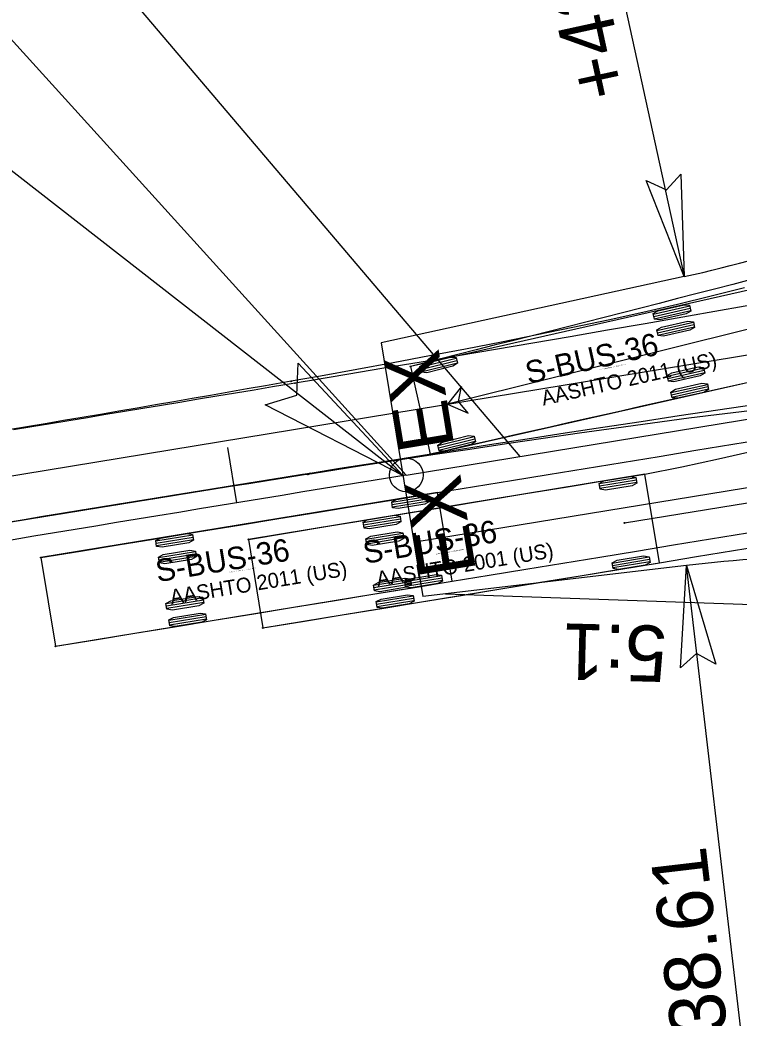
# Model space of a CAD drawing. Extents: x 2367848 to 2369479, y 800728 to 808616.
# Drawn here: x 2368247.5 to 2368311.6, y 807886 to 807974.9 of the extents above; entities that cross this region are included whole.
import ezdxf

# ---------------------------------------------------------------- set-up
doc = ezdxf.new("R2010")
doc.units = 0
for name, color, linetype in [('Prop AutoTurn Projected Path', 7, 'Continuous'), ('Prop AutoTurn Simulation', 7, 'Continuous'), ('Prop Dimension', 7, 'Continuous'), ('Prop Dimension Text', 7, 'Continuous'), ('Prop EOT', 7, 'Continuous'), ('Prop Horizontal Alignment', 7, 'Continuous'), ('Prop Horizontal Alignment Station Label', 7, 'Continuous'), ('Prop Horizontal Alignment Tick Small', 7, 'Continuous'), ('Prop Paved Shoulder', 7, 'Continuous'), ('Prop Terminator CELL', 7, 'Continuous'), ('Scratch_Level_0', 7, 'Continuous'), ('Scratch_Level_1', 7, 'Continuous')]:
    doc.layers.add(name, color=color, linetype=linetype)

msp = doc.modelspace()

# ---------------------------------------------------------------- linework, layer by layer
at = {"layer": 'Prop AutoTurn Projected Path'}
for p, q in [((2368204.585, 807927.346), (2368346.13, 807950.643)), ((2368301.356, 807930.099), (2368335.962, 807935.795))]:
    msp.add_line(p, q, dxfattribs=at)
at = {"layer": 'Prop AutoTurn Simulation'}
for p, q in [((2368303.173, 807934.452), (2368267.848, 807928.638)), ((2368304.472, 807926.558), (2368303.173, 807934.452)), ((2368303.173, 807934.452), (2368303.173, 807934.452)), ((2368302.384, 807934.111), (2368299.095, 807933.57)), ((2368302.418, 807933.905), (2368299.129, 807933.364)), ((2368302.452, 807933.7), (2368299.163, 807933.159)), ((2368281.367, 807930.652), (2368278.078, 807930.11)), ((2368281.401, 807930.446), (2368278.112, 807929.905)), ((2368281.435, 807930.241), (2368278.146, 807929.699)), ((2368281.611, 807929.172), (2368278.322, 807928.63)), ((2368281.645, 807928.966), (2368278.356, 807928.425)), ((2368267.848, 807928.638), (2368269.147, 807920.744)), ((2368281.679, 807928.761), (2368278.389, 807928.219)), ((2368269.147, 807920.744), (2368304.472, 807926.558)), ((2368303.548, 807927.039), (2368300.259, 807926.498)), ((2368303.582, 807926.834), (2368300.293, 807926.293)), ((2368303.616, 807926.628), (2368300.327, 807926.087)), ((2368282.288, 807925.06), (2368278.999, 807924.519)), ((2368282.321, 807924.855), (2368279.032, 807924.313)), ((2368282.355, 807924.649), (2368279.066, 807924.108)), ((2368282.531, 807923.58), (2368279.242, 807923.039)), ((2368282.565, 807923.375), (2368279.276, 807922.833)), ((2368282.599, 807923.169), (2368279.31, 807922.628))]:
    msp.add_line(p, q, dxfattribs=at)
for points in [[(2368312.042, 807951.032), (2368309.084, 807950.286), (2368306.066, 807949.56), (2368302.998, 807948.856), (2368299.89, 807948.17), (2368296.751, 807947.502), (2368293.585, 807946.85), (2368290.399, 807946.213), (2368287.195, 807945.588), (2368283.977, 807944.975), (2368280.748, 807944.371), (2368277.509, 807943.776), (2368274.262, 807943.188), (2368271.66, 807942.723)], [(2368313.273, 807949.613), (2368309.9, 807949.017), (2368306.539, 807948.427), (2368303.189, 807947.843), (2368299.848, 807947.264), (2368296.514, 807946.691), (2368293.186, 807946.121), (2368289.864, 807945.555), (2368286.546, 807944.993), (2368283.233, 807944.433), (2368279.922, 807943.876), (2368276.614, 807943.321), (2368273.309, 807942.767), (2368271.987, 807942.547)], [(2368271.66, 807942.723), (2368271.008, 807942.607), (2368269.379, 807942.319), (2368267.749, 807942.031), (2368266.118, 807941.745), (2368264.485, 807941.461), (2368262.852, 807941.177), (2368261.217, 807940.894), (2368259.582, 807940.612), (2368257.946, 807940.331), (2368256.309, 807940.05), (2368254.672, 807939.771), (2368253.034, 807939.492), (2368251.396, 807939.213), (2368249.757, 807938.935), (2368248.117, 807938.658), (2368246.477, 807938.381)], [(2368271.987, 807942.547), (2368271.657, 807942.491), (2368270.005, 807942.216), (2368268.354, 807941.94), (2368266.704, 807941.665), (2368265.053, 807941.391), (2368263.403, 807941.116), (2368261.754, 807940.842), (2368260.104, 807940.568), (2368258.455, 807940.295), (2368256.806, 807940.021), (2368255.158, 807939.748), (2368253.509, 807939.475), (2368251.861, 807939.202), (2368250.213, 807938.929), (2368248.565, 807938.656), (2368246.917, 807938.384)], [(2368313.119, 807940.657), (2368309.664, 807940.143), (2368306.233, 807939.63), (2368302.823, 807939.116), (2368299.43, 807938.601), (2368296.053, 807938.084), (2368292.689, 807937.564), (2368289.335, 807937.043), (2368285.991, 807936.519), (2368282.655, 807935.993), (2368279.326, 807935.466), (2368276.002, 807934.937), (2368273.347, 807934.512)], [(2368313.496, 807940.212), (2368310.296, 807939.826), (2368307.079, 807939.419), (2368303.848, 807938.992), (2368300.607, 807938.549), (2368297.356, 807938.092), (2368294.098, 807937.622), (2368290.835, 807937.143), (2368287.567, 807936.654), (2368284.295, 807936.158), (2368281.019, 807935.655), (2368277.742, 807935.147), (2368274.461, 807934.634), (2368273.149, 807934.427)], [(2368267.848, 807928.638), (2368271.381, 807929.219), (2368274.913, 807929.801), (2368278.446, 807930.382), (2368281.978, 807930.963), (2368285.511, 807931.545), (2368289.043, 807932.126), (2368292.576, 807932.708), (2368296.108, 807933.289), (2368299.64, 807933.871), (2368303.172, 807934.455), (2368303.172, 807934.455), (2368306.452, 807935.098), (2368309.726, 807935.801), (2368313, 807936.559)], [(2368273.347, 807934.512), (2368272.683, 807934.406), (2368271.025, 807934.14), (2368269.369, 807933.873), (2368267.713, 807933.607), (2368266.058, 807933.34), (2368264.403, 807933.073), (2368262.75, 807932.805), (2368261.097, 807932.538), (2368259.445, 807932.27), (2368257.793, 807932.002), (2368256.142, 807931.734), (2368254.491, 807931.465), (2368252.84, 807931.197), (2368251.191, 807930.928), (2368249.541, 807930.659), (2368247.892, 807930.39), (2368246.243, 807930.121)], [(2368273.149, 807934.427), (2368272.821, 807934.376), (2368271.18, 807934.117), (2368269.538, 807933.857), (2368267.896, 807933.596), (2368266.254, 807933.334), (2368264.612, 807933.072), (2368262.969, 807932.809), (2368261.326, 807932.546), (2368259.683, 807932.282), (2368258.039, 807932.017), (2368256.396, 807931.752), (2368254.752, 807931.486), (2368253.108, 807931.221), (2368251.464, 807930.954), (2368249.82, 807930.688), (2368248.175, 807930.421), (2368246.531, 807930.154)], [(2368269.147, 807920.744), (2368272.68, 807921.325), (2368276.212, 807921.907), (2368279.745, 807922.488), (2368283.277, 807923.07), (2368286.81, 807923.651), (2368290.342, 807924.232), (2368293.875, 807924.814), (2368297.407, 807925.395), (2368300.94, 807925.977), (2368304.472, 807926.558), (2368304.472, 807926.558), (2368304.472, 807926.558), (2368307.768, 807927.101), (2368311.064, 807927.643), (2368314.36, 807928.186)]]:
    msp.add_lwpolyline(points, dxfattribs=at)
for points in [[(2368302.376, 807934.162), (2368302.461, 807933.649), (2368302.026, 807933.419), (2368299.657, 807933.029), (2368299.171, 807933.108), (2368299.087, 807933.621), (2368299.522, 807933.851), (2368301.89, 807934.241)], [(2368281.359, 807930.703), (2368281.443, 807930.19), (2368281.008, 807929.959), (2368278.64, 807929.569), (2368278.154, 807929.648), (2368278.07, 807930.161), (2368278.505, 807930.392), (2368280.873, 807930.782)], [(2368281.602, 807929.223), (2368281.687, 807928.71), (2368281.252, 807928.479), (2368278.884, 807928.089), (2368278.398, 807928.168), (2368278.313, 807928.681), (2368278.748, 807928.912), (2368281.117, 807929.301)], [(2368303.54, 807927.09), (2368303.624, 807926.577), (2368303.189, 807926.347), (2368300.821, 807925.957), (2368300.335, 807926.036), (2368300.251, 807926.549), (2368300.686, 807926.779), (2368303.054, 807927.169)], [(2368282.279, 807925.111), (2368282.364, 807924.598), (2368281.929, 807924.368), (2368279.56, 807923.978), (2368279.075, 807924.057), (2368278.99, 807924.57), (2368279.425, 807924.8), (2368281.793, 807925.19)], [(2368282.523, 807923.631), (2368282.607, 807923.118), (2368282.172, 807922.888), (2368279.804, 807922.498), (2368279.318, 807922.577), (2368279.234, 807923.09), (2368279.669, 807923.32), (2368282.037, 807923.71)]]:
    msp.add_lwpolyline(points, close=True, dxfattribs=at)
for centre in [(2368271.66, 807942.723), (2368271.66, 807942.723), (2368271.987, 807942.547), (2368271.987, 807942.547), (2368273.149, 807934.427), (2368273.149, 807934.427), (2368273.347, 807934.512), (2368273.347, 807934.512), (2368301.356, 807930.099), (2368267.848, 807928.638), (2368269.147, 807920.744)]:
    msp.add_circle(centre, 0.0417, dxfattribs=at)
at = {"layer": 'Prop Dimension'}
msp.add_line((2368188.721, 808006.686), (2368281.621, 807934.321), dxfattribs=at)
at = {"layer": 'Prop Dimension Text'}
for p, q in [((2368281.057, 808069.281), (2368306.681, 807952.049)), ((2368320.889, 807807.139), (2368306.862, 807926.316))]:
    msp.add_line(p, q, dxfattribs=at)
at = {"layer": 'Prop EOT'}
for p, q in [((2368306.681, 807952.049), (2368279.684, 807946.148)), ((2368279.684, 807946.148), (2368283.386, 807923.553)), ((2368306.862, 807926.316), (2368283.386, 807923.553))]:
    msp.add_line(p, q, dxfattribs=at)
for centre, start, end in [((2368281.057, 808069.281), 282.32916, 295.16773), ((2368320.889, 807807.139), 83.87456, 96.71313)]:
    msp.add_arc(centre, 120, start, end, dxfattribs=at)
at = {"layer": 'Prop Horizontal Alignment'}
msp.add_line((2368281.913, 807934.369), (2368381.597, 807950.7), dxfattribs=at)
msp.add_arc((2371987.159, 785317.557), 22918.312, 99.3039502, 99.4533454, dxfattribs=at)
at = {"layer": 'Prop Horizontal Alignment Station Label'}
for p, q in [((2368226.441, 808013.246), (2368292.043, 807936.028)), ((2368281.913, 807934.369), (2368211.37, 808012.133))]:
    msp.add_line(p, q, dxfattribs=at)
msp.add_circle((2368281.913, 807934.369), 1.5, dxfattribs=at)
at = {"layer": 'Prop Horizontal Alignment Tick Small'}
msp.add_line((2368266.82, 807931.891), (2368266.008, 807936.824), dxfattribs=at)
at = {"layer": 'Prop Paved Shoulder'}
msp.add_line((2368285.416, 807923.792), (2368324.578, 807922.42), dxfattribs=at)
at = {"layer": 'Prop Terminator CELL'}
for points in [[(2368306.375, 807961.176), (2368306.681, 807952.049), (2368303.28, 807960.587), (2368305.08, 807959.785)], [(2368272.271, 807944.332), (2368281.621, 807934.321), (2368269.355, 807940.612), (2368272.18, 807941.482)], [(2368306.347, 807917.198), (2368306.862, 807926.316), (2368309.482, 807917.507), (2368307.761, 807918.467)]]:
    msp.add_lwpolyline(points, close=True, dxfattribs=at)
at = {"layer": 'Scratch_Level_0'}
for p, q in [((2368354.563, 807957.874), (2368285.597, 807940.681)), ((2368317.2, 807951.912), (2368282.278, 807944.032)), ((2368303.914, 807948.701), (2368307.166, 807949.434)), ((2368303.96, 807948.497), (2368307.211, 807949.231)), ((2368304.006, 807948.294), (2368307.257, 807949.028)), ((2368304.244, 807947.237), (2368307.496, 807947.971)), ((2368304.29, 807947.034), (2368307.542, 807947.768)), ((2368304.336, 807946.831), (2368307.587, 807947.565)), ((2368282.278, 807944.032), (2368284.038, 807936.229)), ((2368283.131, 807943.973), (2368286.366, 807944.779)), ((2368283.182, 807943.771), (2368286.416, 807944.577)), ((2368283.232, 807943.569), (2368286.466, 807944.375)), ((2368284.038, 807936.229), (2368318.96, 807944.108)), ((2368305.161, 807943.173), (2368308.413, 807943.907)), ((2368305.207, 807942.97), (2368308.459, 807943.703)), ((2368305.253, 807942.766), (2368308.505, 807943.5)), ((2368305.491, 807941.71), (2368308.743, 807942.443)), ((2368305.537, 807941.507), (2368308.789, 807942.24)), ((2368305.583, 807941.303), (2368308.835, 807942.037)), ((2368284.727, 807936.986), (2368287.961, 807937.793)), ((2368284.777, 807936.784), (2368288.012, 807937.591)), ((2368284.828, 807936.582), (2368288.062, 807937.389)), ((2368284.038, 807936.229), (2368284.038, 807936.229))]:
    msp.add_line(p, q, dxfattribs=at)
for points in [[(2368312.642, 807951.771), (2368310.997, 807951.346), (2368309.355, 807950.922), (2368307.715, 807950.499), (2368306.076, 807950.078), (2368304.439, 807949.658), (2368302.803, 807949.239), (2368301.169, 807948.821), (2368299.536, 807948.404), (2368297.904, 807947.988), (2368296.272, 807947.573), (2368294.642, 807947.159), (2368293.013, 807946.746), (2368291.385, 807946.333), (2368289.757, 807945.921), (2368288.13, 807945.509), (2368286.504, 807945.098), (2368284.878, 807944.688), (2368283.252, 807944.278), (2368282.278, 807944.032)], [(2368312.393, 807942.611), (2368310.795, 807942.259), (2368309.195, 807941.903), (2368307.594, 807941.543), (2368305.99, 807941.182), (2368304.384, 807940.819), (2368302.777, 807940.457), (2368301.168, 807940.093), (2368299.557, 807939.73), (2368297.945, 807939.366), (2368296.332, 807939.002), (2368294.717, 807938.638), (2368293.101, 807938.274), (2368291.485, 807937.909), (2368289.867, 807937.544), (2368288.249, 807937.179), (2368286.63, 807936.813), (2368285.01, 807936.448), (2368284.038, 807936.229)]]:
    msp.add_lwpolyline(points, dxfattribs=at)
for points in [[(2368304.017, 807948.244), (2368303.903, 807948.751), (2368304.323, 807949.007), (2368306.665, 807949.535), (2368307.154, 807949.485), (2368307.269, 807948.977), (2368306.848, 807948.722), (2368304.507, 807948.194)], [(2368304.347, 807946.781), (2368304.233, 807947.288), (2368304.654, 807947.543), (2368306.995, 807948.072), (2368307.484, 807948.021), (2368307.599, 807947.514), (2368307.178, 807947.259), (2368304.837, 807946.73)], [(2368283.245, 807943.519), (2368283.119, 807944.023), (2368283.534, 807944.288), (2368285.863, 807944.869), (2368286.353, 807944.829), (2368286.479, 807944.325), (2368286.064, 807944.06), (2368283.735, 807943.48)], [(2368305.264, 807942.716), (2368305.15, 807943.223), (2368305.571, 807943.479), (2368307.912, 807944.007), (2368308.401, 807943.957), (2368308.516, 807943.45), (2368308.095, 807943.194), (2368305.754, 807942.666)], [(2368285.597, 807940.681), (2368287.431, 807939.883), (2368286.567, 807940.923), (2368286.842, 807942.246)], [(2368305.594, 807941.253), (2368305.48, 807941.76), (2368305.901, 807942.016), (2368308.242, 807942.544), (2368308.732, 807942.494), (2368308.846, 807941.987), (2368308.425, 807941.731), (2368306.084, 807941.203)], [(2368284.84, 807936.532), (2368284.714, 807937.036), (2368285.129, 807937.301), (2368287.458, 807937.882), (2368287.949, 807937.843), (2368288.074, 807937.338), (2368287.66, 807937.074), (2368285.331, 807936.493)]]:
    msp.add_lwpolyline(points, close=True, dxfattribs=at)
for centre in [(2368282.278, 807944.032), (2368285.597, 807940.681), (2368284.038, 807936.229)]:
    msp.add_circle(centre, 0.0417, dxfattribs=at)
at = {"layer": 'Scratch_Level_1'}
for p, q in [((2368282.883, 807928.448), (2368360.8, 807941.212)), ((2368284.703, 807932.799), (2368249.374, 807927.011)), ((2368283.915, 807932.459), (2368280.625, 807931.92)), ((2368285.997, 807924.904), (2368284.703, 807932.799)), ((2368284.703, 807932.799), (2368284.703, 807932.799)), ((2368283.948, 807932.253), (2368280.659, 807931.714)), ((2368283.982, 807932.048), (2368280.693, 807931.509)), ((2368262.895, 807929.015), (2368259.605, 807928.476)), ((2368262.929, 807928.81), (2368259.639, 807928.271)), ((2368262.962, 807928.604), (2368259.673, 807928.065)), ((2368263.137, 807927.535), (2368259.848, 807926.996)), ((2368263.171, 807927.329), (2368259.882, 807926.79)), ((2368263.205, 807927.124), (2368259.915, 807926.585)), ((2368249.374, 807927.011), (2368250.668, 807919.117)), ((2368285.073, 807925.386), (2368281.784, 807924.848)), ((2368250.668, 807919.117), (2368285.997, 807924.904)), ((2368285.107, 807925.181), (2368281.817, 807924.642)), ((2368285.141, 807924.975), (2368281.851, 807924.436)), ((2368263.811, 807923.423), (2368260.522, 807922.884)), ((2368263.845, 807923.217), (2368260.555, 807922.679)), ((2368263.878, 807923.012), (2368260.589, 807922.473)), ((2368264.054, 807921.943), (2368260.764, 807921.404)), ((2368264.087, 807921.737), (2368260.798, 807921.198)), ((2368264.121, 807921.532), (2368260.831, 807920.993))]:
    msp.add_line(p, q, dxfattribs=at)
for points in [[(2368249.374, 807927.011), (2368252.907, 807927.59), (2368256.44, 807928.169), (2368259.973, 807928.748), (2368263.506, 807929.326), (2368267.039, 807929.905), (2368270.572, 807930.484), (2368274.105, 807931.063), (2368277.638, 807931.642), (2368281.17, 807932.22), (2368284.703, 807932.799), (2368284.703, 807932.799), (2368287.991, 807933.338), (2368291.279, 807933.876), (2368294.566, 807934.415), (2368297.854, 807934.954), (2368301.142, 807935.492), (2368304.429, 807936.031), (2368307.717, 807936.569), (2368311.004, 807937.108), (2368314.292, 807937.647)], [(2368250.668, 807919.117), (2368254.201, 807919.695), (2368257.733, 807920.274), (2368261.266, 807920.853), (2368264.799, 807921.432), (2368268.332, 807922.01), (2368271.865, 807922.589), (2368275.398, 807923.168), (2368278.931, 807923.747), (2368282.464, 807924.326), (2368285.997, 807924.904), (2368285.997, 807924.904), (2368285.997, 807924.904), (2368289.284, 807925.443), (2368292.572, 807925.982), (2368295.86, 807926.52), (2368299.147, 807927.059), (2368302.435, 807927.597), (2368305.723, 807928.136), (2368309.01, 807928.675), (2368312.298, 807929.213)]]:
    msp.add_lwpolyline(points, dxfattribs=at)
for points in [[(2368283.906, 807932.51), (2368283.99, 807931.997), (2368283.555, 807931.767), (2368281.187, 807931.379), (2368280.701, 807931.458), (2368280.617, 807931.971), (2368281.052, 807932.201), (2368283.42, 807932.589)], [(2368262.887, 807929.066), (2368262.971, 807928.553), (2368262.535, 807928.323), (2368260.167, 807927.935), (2368259.681, 807928.014), (2368259.597, 807928.527), (2368260.032, 807928.757), (2368262.401, 807929.145)], [(2368263.129, 807927.586), (2368263.213, 807927.073), (2368262.778, 807926.843), (2368260.409, 807926.455), (2368259.924, 807926.534), (2368259.84, 807927.047), (2368260.275, 807927.277), (2368262.643, 807927.665)], [(2368285.065, 807925.437), (2368285.149, 807924.924), (2368284.714, 807924.694), (2368282.345, 807924.306), (2368281.86, 807924.385), (2368281.775, 807924.898), (2368282.211, 807925.129), (2368284.579, 807925.517)], [(2368263.803, 807923.474), (2368263.887, 807922.961), (2368263.452, 807922.731), (2368261.083, 807922.343), (2368260.597, 807922.422), (2368260.513, 807922.935), (2368260.948, 807923.165), (2368263.317, 807923.553)], [(2368264.045, 807921.994), (2368264.129, 807921.481), (2368263.694, 807921.251), (2368261.326, 807920.863), (2368260.84, 807920.942), (2368260.756, 807921.455), (2368261.191, 807921.685), (2368263.559, 807922.073)]]:
    msp.add_lwpolyline(points, close=True, dxfattribs=at)
for centre in [(2368282.883, 807928.448), (2368249.374, 807927.011), (2368250.668, 807919.117)]:
    msp.add_circle(centre, 0.0417, dxfattribs=at)

# ---------------------------------------------------------------- texts
at = {"layer": 'Prop AutoTurn Simulation'}
for s, height, p in [('S-BUS-36', 2, (2368278.24, 807926.457)), ('AASHTO 2001 (US)', 1.33333, (2368279.368, 807924.446)), ('(c) 2014 Transoft Solutions, Inc. All rights reserved.', 0.08, (2368284.558, 807927.294))]:
    msp.add_text(s, height=height, rotation=9.34665, dxfattribs=at).set_placement(p)
at = {"layer": 'Prop Dimension'}
for p in [(2368286.218, 807936.908), (2368288.148, 807925.774)]:
    msp.add_text('EX', height=5, rotation=99.34665, dxfattribs=at).set_placement(p)
at = {"layer": 'Prop Dimension Text'}
for s, rotation, p in [('+42.60', 102.32916, (2368301.796, 807968.386)), ('5:1', 178.54389, (2368305.192, 807920.921)), ('+38.61', 96.71313, (2368310.987, 807880.932))]:
    msp.add_text(s, height=5, rotation=rotation, dxfattribs=at).set_placement(p)
at = {"layer": 'Scratch_Level_0'}
for s, height, p in [('S-BUS-36', 2, (2368292.78, 807942.466)), ('AASHTO 2011 (US)', 1.33333, (2368294.116, 807940.546)), ('(c) 2016 Transoft Solutions, Inc. All rights reserved.', 0.08, (2368299.037, 807943.672))]:
    msp.add_text(s, height=height, rotation=12.71458, dxfattribs=at).set_placement(p)
at = {"layer": 'Scratch_Level_1'}
for s, height, p in [('S-BUS-36', 2, (2368259.765, 807924.822)), ('AASHTO 2011 (US)', 1.33333, (2368260.985, 807922.827)), ('(c) 2016 Transoft Solutions, Inc. All rights reserved.', 0.08, (2368266.083, 807925.655))]:
    msp.add_text(s, height=height, rotation=9.30395, dxfattribs=at).set_placement(p)

doc.saveas('drawing.dxf')
